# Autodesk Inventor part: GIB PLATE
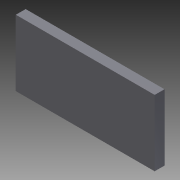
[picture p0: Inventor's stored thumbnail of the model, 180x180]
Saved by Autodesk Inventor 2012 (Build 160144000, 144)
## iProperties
Shininess: 64.0
Length Units: 11272
Angle Units: 11279
Time Units: 11290
Mass Units: 11286
Length Display Precision: 3
Angle Display Precision: 2
Compacted: True
Part Number: GIB PLATE
Document SubType Name: Modeling
Created: 2003-11
Designer: Autodesk, Inc.
Manufacturer: Standard
Standards Organization: Custom
Mass: 9.82621 g
Surface Area: 12.9097 cm^2
Volume: 1.25015 cm^3
Density: 7.86 g/cm^3
Material: Steel, Mild
Density: 0.0
Volumn: 0.0
Area: 0.0
PropertySet Name: Model Information
Control State: 0
Master: False
Checked Out: False
Author: Autodesk, Inc.
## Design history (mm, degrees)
sketch "Sketch1"
  geometry: L1 (0, 0)-(33.338, 0); L2 (33.338, 0)-(33.338, 15.875); L3 (33.338, 15.875)-(0, 15.875); L4 (0, 15.875)-(0, 0)
  constraints: 8 end point, 2 parallel, 1 horizontal, 1 perpendicular
  dimensions: "d0" = 33.3375 distance of L1.start L1.end; "d1" = 15.875 distance between parallel lines of L1 L3
extrude "Extrusion1" new body sketch "Sketch1" distance "d2" = 2.3622; taper "d3" = 0 deg
body "Solid1"
